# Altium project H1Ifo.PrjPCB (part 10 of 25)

## Sheet IfoIsc5A.SchDoc: D1800185
size C; Engineer: Daniel Sigg; DocumentNumber: 9; Revision: 4; SheetNumber: 9; SheetTotal: 11
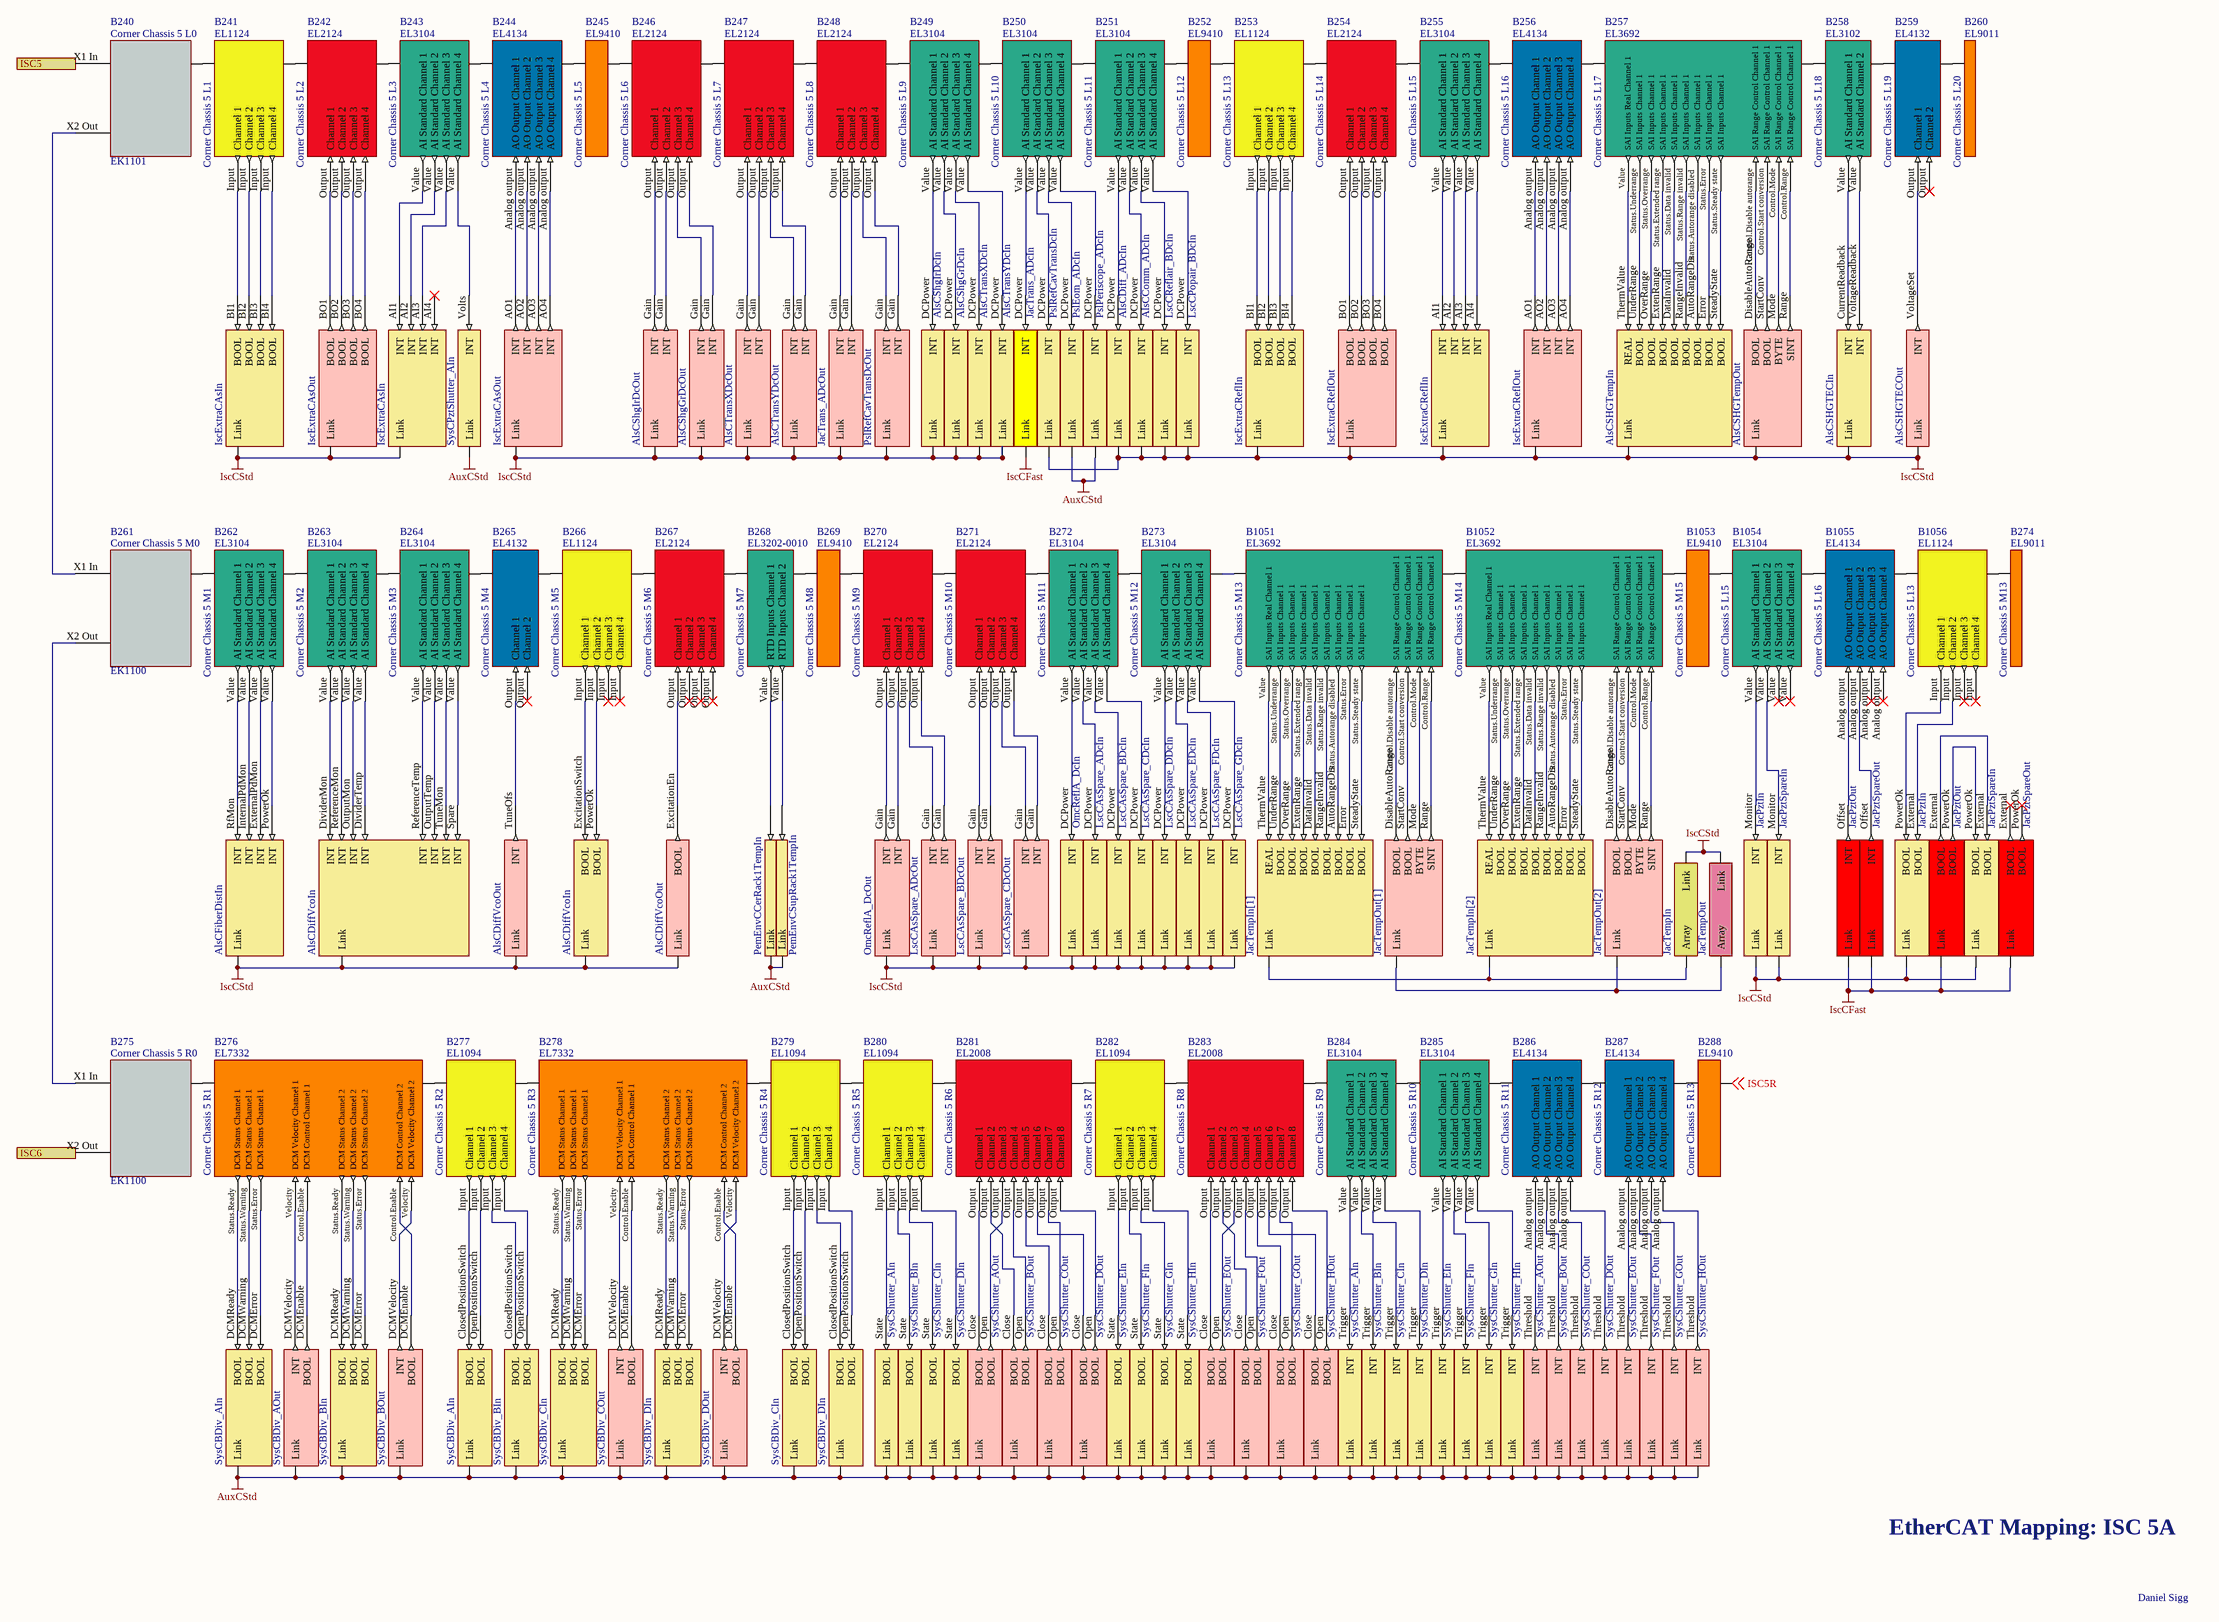
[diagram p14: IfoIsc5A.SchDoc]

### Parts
B240  Corner Chassis 5 L0  Part Number: EK1101  (mechanical)
B241  Corner Chassis 5 L1  Part Number: EL1124  (mechanical)
B242  Corner Chassis 5 L2  Part Number: EL2124  (mechanical)
B243  Corner Chassis 5 L3  Part Number: EL3104  (mechanical)
B244  Corner Chassis 5 L4  Part Number: EL4134  (mechanical)
B245  Corner Chassis 5 L5  Part Number: EL9410  (mechanical)
B246  Corner Chassis 5 L6  Part Number: EL2124  (mechanical)
B247  Corner Chassis 5 L7  Part Number: EL2124  (mechanical)
B248  Corner Chassis 5 L8  Part Number: EL2124  (mechanical)
B249  Corner Chassis 5 L9  Part Number: EL3104  (mechanical)
B250  Corner Chassis 5 L10  Part Number: EL3104  (mechanical)
B251  Corner Chassis 5 L11  Part Number: EL3104  (mechanical)
B252  Corner Chassis 5 L12  Part Number: EL9410  (mechanical)
B253  Corner Chassis 5 L13  Part Number: EL1124  (mechanical)
B254  Corner Chassis 5 L14  Part Number: EL2124  (mechanical)
B255  Corner Chassis 5 L15  Part Number: EL3104  (mechanical)
B256  Corner Chassis 5 L16  Part Number: EL4134  (mechanical)
B257  Corner Chassis 5 L17  Part Number: EL3692  (mechanical)
B258  Corner Chassis 5 L18  Part Number: EL3102  (mechanical)
B259  Corner Chassis 5 L19  Part Number: EL4132  (mechanical)
B260  Corner Chassis 5 L20  Part Number: EL9011  (mechanical)
B261  Corner Chassis 5 M0  Part Number: EK1100  (mechanical)
B262  Corner Chassis 5 M1  Part Number: EL3104  (mechanical)
B263  Corner Chassis 5 M2  Part Number: EL3104  (mechanical)
B264  Corner Chassis 5 M3  Part Number: EL3104  (mechanical)
B265  Corner Chassis 5 M4  Part Number: EL4132  (mechanical)
B266  Corner Chassis 5 M5  Part Number: EL1124  (mechanical)
B267  Corner Chassis 5 M6  Part Number: EL2124  (mechanical)
B268  Corner Chassis 5 M7  Part Number: EL3202-0010  (mechanical)
B269  Corner Chassis 5 M8  Part Number: EL9410  (mechanical)
B270  Corner Chassis 5 M9  Part Number: EL2124  (mechanical)
B271  Corner Chassis 5 M10  Part Number: EL2124  (mechanical)
B272  Corner Chassis 5 M11  Part Number: EL3104  (mechanical)
B273  Corner Chassis 5 M12  Part Number: EL3104  (mechanical)
B274  Corner Chassis 5 M13  Part Number: EL9011  (mechanical)
B275  Corner Chassis 5 R0  Part Number: EK1100  (mechanical)
B276  Corner Chassis 5 R1  Part Number: EL7332  (mechanical)
B277  Corner Chassis 5 R2  Part Number: EL1094  (mechanical)
B278  Corner Chassis 5 R3  Part Number: EL7332  (mechanical)
B279  Corner Chassis 5 R4  Part Number: EL1094  (mechanical)
B280  Corner Chassis 5 R5  Part Number: EL1094  (mechanical)
B281  Corner Chassis 5 R6  Part Number: EL2008  (mechanical)
B282  Corner Chassis 5 R7  Part Number: EL1094  (mechanical)
B283  Corner Chassis 5 R8  Part Number: EL2008  (mechanical)
B284  Corner Chassis 5 R9  Part Number: EL3104  (mechanical)
B285  Corner Chassis 5 R10  Part Number: EL3104  (mechanical)
B286  Corner Chassis 5 R11  Part Number: EL4134  (mechanical)
B287  Corner Chassis 5 R12  Part Number: EL4134  (mechanical)
B288  Corner Chassis 5 R13  Part Number: EL9410  (mechanical)
B1051  Corner Chassis 5 M13  Part Number: EL3692  (mechanical)
B1052  Corner Chassis 5 M14  Part Number: EL3692  (mechanical)
B1053  Corner Chassis 5 M15  Part Number: EL9410  (mechanical)
B1054  Corner Chassis 5 L15  Part Number: EL3104  (mechanical)
B1055  Corner Chassis 5 L16  Part Number: EL4134  (mechanical)
B1056  Corner Chassis 5 L13  Part Number: EL1124  (mechanical)
V215  SysCShutter_AIn  (parts A,B of 2)  (no BOM)
V216  SysCShutter_BIn  (parts A,B of 2)  (no BOM)
V217  SysCShutter_CIn  (parts A,B of 2)  (no BOM)
V218  SysCShutter_DIn  (parts A,B of 2)  (no BOM)
V219  SysCShutter_AOut  (parts A,B of 2)  (no BOM)
V220  SysCShutter_BOut  (parts A,B of 2)  (no BOM)
V221  SysCShutter_COut  (parts A,B of 2)  (no BOM)
V222  SysCShutter_DOut  (parts A,B of 2)  (no BOM)
V223  SysCShutter_EIn  (parts A,B of 2)  (no BOM)
V224  SysCShutter_FIn  (parts A,B of 2)  (no BOM)
V225  SysCShutter_GIn  (parts A,B of 2)  (no BOM)
V226  SysCShutter_HIn  (parts A,B of 2)  (no BOM)
V228  SysCShutter_EOut  (parts A,B of 2)  (no BOM)
V229  SysCShutter_FOut  (parts A,B of 2)  (no BOM)
V230  SysCShutter_GOut  (parts A,B of 2)  (no BOM)
V231  SysCShutter_HOut  (parts A,B of 2)  (no BOM)
V232  SysCBDiv_AIn  (parts A,B of 2)  (no BOM)
V233  SysCBDiv_BIn  (parts A,B of 2)  (no BOM)
V234  SysCBDiv_CIn  (parts A,B of 2)  (no BOM)
V235  SysCBDiv_DIn  (parts A,B of 2)  (no BOM)
V238  AlsCDiffVcoIn  (parts A,B of 2)  (no BOM)
V335  IscExtraCAsIn  (parts A,B of 2)  (no BOM)
V336  IscExtraCAsOut  (parts A,B of 2)  (no BOM)
V337  SysCPztShutter_AIn  (no BOM)
V338  AlsCShgIrDcOut  (no BOM)
V339  AlsCShgGrDcOut  (no BOM)
V340  AlsCTransXDcOut  (no BOM)
V341  AlsCTransYDcOut  (no BOM)
V342  JacTrans_ADcOut  (no BOM)
V343  PslRefCavTransDcOut  (no BOM)
V344  AlsCShgIrDcIn  (no BOM)
V345  AlsCShgGrDcIn  (no BOM)
V346  AlsCTransXDcIn  (no BOM)
V347  AlsCTransYDcIn  (no BOM)
V348  JacTrans_ADcIn  (no BOM)
V349  PslRefCavTransDcIn  (no BOM)
V350  PslEom_ADcIn  (no BOM)
V351  PslPeriscope_ADcIn  (no BOM)
V352  AlsCDiff_ADcIn  (no BOM)
V353  AlsCComm_ADcIn  (no BOM)
V354  LscCReflair_BDcIn  (no BOM)
V355  LscCPopair_BDcIn  (no BOM)
V376  IscExtraCReflIn  (parts A,B of 2)  (no BOM)
V377  IscExtraCReflOut  (parts A,B of 2)  (no BOM)
V378  AlsCFiberDistIn  (no BOM)
V379  AlsCDiffVcoOut  (parts A,B of 2)  (no BOM)
V382  PemEnvCCerRack1TempIn  (no BOM)
V383  PemEnvCSupRack1TempIn  (no BOM)
V384  LscCAsSpare_ADcOut  (no BOM)
V385  LscCAsSpare_BDcOut  (no BOM)
V386  LscCAsSpare_CDcOut  (no BOM)
V387  OmcReflA_DcOut  (no BOM)
V388  LscCAsSpare_ADcIn  (no BOM)
V389  LscCAsSpare_BDcIn  (no BOM)
V390  LscCAsSpare_CDcIn  (no BOM)
V391  LscCAsSpare_DDcIn  (no BOM)
V392  LscCAsSpare_EDcIn  (no BOM)
V393  LscCAsSpare_FDcIn  (no BOM)
V394  LscCAsSpare_GDcIn  (no BOM)
V395  OmcReflA_DcIn  (no BOM)
V396  SysCBDiv_AOut  (no BOM)
V397  SysCBDiv_BOut  (no BOM)
V398  SysCBDiv_COut  (no BOM)
V399  SysCBDiv_DOut  (no BOM)
V717  AlsCSHGTECIn  (no BOM)
V718  AlsCSHGTECOut  (no BOM)
V719  AlsCSHGTempIn  (no BOM)
V720  AlsCSHGTempOut  (no BOM)
V896  JacTempIn[1]  (no BOM)
V897  JacTempOut[1]  (no BOM)
V898  JacTempIn[2]  (no BOM)
V899  JacTempOut[2]  (no BOM)
V902  JacPztIn  (parts A,B of 2)  (no BOM)
V903  JacPztSpareIn  (parts A,B of 2)  (no BOM)
V904  JacPztOut  (parts A,B of 2)  (no BOM)
V905  JacPztSpareOut  (parts A,B of 2)  (no BOM)
V906  JacTempIn  (no BOM)
V907  JacTempOut  (no BOM)

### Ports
ISC5, ISC6

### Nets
AuxCStd: V215.0(Link) V215.1(Link) V216.0(Link) V216.1(Link) V217.0(Link) V217.1(Link) V218.0(Link) V218.1(Link) V219.0(Link) V219.1(Link) V220.0(Link) V220.1(Link) V221.0(Link) V221.1(Link) V222.0(Link) V222.1(Link) V223.0(Link) V223.1(Link) V224.0(Link) V224.1(Link) V225.0(Link) V225.1(Link) V226.0(Link) V226.1(Link) V228.0(Link) V228.1(Link) V229.0(Link) V229.1(Link) V230.0(Link) V230.1(Link) V231.0(Link) V231.1(Link) V232.0(Link) V232.1(Link) V233.0(Link) V233.1(Link) V234.0(Link) V234.1(Link) V235.0(Link) V235.1(Link) V337.1(Link) V350.1(Link) V351.1(Link) V382.?2(Link) V383.?2(Link) V396.0(Link) V397.0(Link) V398.0(Link) V399.0(Link)
IscCFast: V348.1(Link) V904.0(Link) V904.1(Link) V905.0(Link) V905.1(Link)
IscCStd: V238.0(Link) V238.1(Link) V335.0(Link) V335.1(Link) V336.0(Link) V336.1(Link) V338.0(Link) V339.0(Link) V340.0(Link) V341.0(Link) V342.0(Link) V343.0(Link) V344.1(Link) V345.1(Link) V346.1(Link) V347.1(Link) V349.1(Link) V352.1(Link) V353.1(Link) V354.1(Link) V355.1(Link) V376.0(Link) V376.1(Link) V377.0(Link) V377.1(Link) V378.1(Link) V379.0(Link) V379.1(Link) V384.0(Link) V385.0(Link) V386.0(Link) V387.0(Link) V388.1(Link) V389.1(Link) V390.1(Link) V391.1(Link) V392.1(Link) V393.1(Link) V394.1(Link) V395.1(Link) V717.1(Link) V718.1(Link) V719.1(Link) V720.1(Link) V902.0(Link) V902.1(Link) V903.0(Link) V903.1(Link) V906.?1(Link) V907.?1(Link)
ISC5R: B288.Ebus(B) ; off-sheet ISC5R
NetB234_X2 Out: B240.X1_In(A) ; port ISC5
NetB240_Ebus: B240.Ebus(B) B241.Ebus(A)
NetB240_X2 Out: B240.X2_Out(C) B261.X1_In(A)
NetB241_Ebus: B241.Ebus(B) B242.Ebus(A)
NetB241_Input: B241.Input(Channel_1) V335.BI1(BOOL)
NetB241_Input: B241.Input(Channel_2) V335.BI2(BOOL)  [a separate net that carries the same name]
NetB241_Input: B241.Input(Channel_3) V335.BI3(BOOL)  [a separate net that carries the same name]
NetB241_Input: B241.Input(Channel_4) V335.BI4(BOOL)  [a separate net that carries the same name]
NetB242_Ebus: B242.Ebus(B) B243.Ebus(A)
NetB242_Output: B242.Output(Channel_1) V336.BO1(BOOL)
NetB242_Output: B242.Output(Channel_2) V336.BO2(BOOL)  [a separate net that carries the same name]
NetB242_Output: B242.Output(Channel_3) V336.BO3(BOOL)  [a separate net that carries the same name]
NetB242_Output: B242.Output(Channel_4) V336.BO4(BOOL)  [a separate net that carries the same name]
NetB243_Ebus: B243.Ebus(B) B244.Ebus(A)
NetB243_Value: B243.Value(AI_Standard_Channel_1) V335.AI1(INT)
NetB243_Value: B243.Value(AI_Standard_Channel_2) V335.AI2(INT)  [a separate net that carries the same name]
NetB243_Value: B243.Value(AI_Standard_Channel_3) V335.AI3(INT)  [a separate net that carries the same name]
NetB243_Value: B243.Value(AI_Standard_Channel_4) V337.Volts(INT)  [a separate net that carries the same name]
NetB244_Analog output: B244.Analog_output(AO_Output_Channel_1) V336.AO1(INT)
NetB244_Analog output: B244.Analog_output(AO_Output_Channel_2) V336.AO2(INT)  [a separate net that carries the same name]
NetB244_Analog output: B244.Analog_output(AO_Output_Channel_3) V336.AO3(INT)  [a separate net that carries the same name]
NetB244_Analog output: B244.Analog_output(AO_Output_Channel_4) V336.AO4(INT)  [a separate net that carries the same name]
NetB244_Ebus: B244.Ebus(B) B245.Ebus(A)
NetB245_Ebus: B245.Ebus(B) B246.Ebus(A)
NetB246_Ebus: B246.Ebus(B) B247.Ebus(A)
NetB246_Output: B246.Output(Channel_1) V338.Gain(INT)
NetB246_Output: B246.Output(Channel_2) V338.Gain(INT)  [a separate net that carries the same name]
NetB246_Output: B246.Output(Channel_3) V339.Gain(INT)  [a separate net that carries the same name]
NetB246_Output: B246.Output(Channel_4) V339.Gain(INT)  [a separate net that carries the same name]
NetB247_Ebus: B247.Ebus(B) B248.Ebus(A)
NetB247_Output: B247.Output(Channel_1) V340.Gain(INT)
NetB247_Output: B247.Output(Channel_2) V340.Gain(INT)  [a separate net that carries the same name]
NetB247_Output: B247.Output(Channel_3) V341.Gain(INT)  [a separate net that carries the same name]
NetB247_Output: B247.Output(Channel_4) V341.Gain(INT)  [a separate net that carries the same name]
NetB248_Ebus: B248.Ebus(B) B249.Ebus(A)
NetB248_Output: B248.Output(Channel_1) V342.Gain(INT)
NetB248_Output: B248.Output(Channel_2) V342.Gain(INT)  [a separate net that carries the same name]
NetB248_Output: B248.Output(Channel_3) V343.Gain(INT)  [a separate net that carries the same name]
NetB248_Output: B248.Output(Channel_4) V343.Gain(INT)  [a separate net that carries the same name]
NetB249_Ebus: B249.Ebus(B) B250.Ebus(A)
NetB249_Value: B249.Value(AI_Standard_Channel_1) V344.DCPower(INT)
NetB249_Value: B249.Value(AI_Standard_Channel_2) V345.DCPower(INT)  [a separate net that carries the same name]
NetB249_Value: B249.Value(AI_Standard_Channel_3) V346.DCPower(INT)  [a separate net that carries the same name]
NetB249_Value: B249.Value(AI_Standard_Channel_4) V347.DCPower(INT)  [a separate net that carries the same name]
NetB250_Ebus: B250.Ebus(B) B251.Ebus(A)
NetB250_Value: B250.Value(AI_Standard_Channel_1) V348.DCPower(INT)
NetB250_Value: B250.Value(AI_Standard_Channel_2) V349.DCPower(INT)  [a separate net that carries the same name]
NetB250_Value: B250.Value(AI_Standard_Channel_3) V350.DCPower(INT)  [a separate net that carries the same name]
NetB250_Value: B250.Value(AI_Standard_Channel_4) V351.DCPower(INT)  [a separate net that carries the same name]
NetB251_Ebus: B251.Ebus(B) B252.Ebus(A)
NetB251_Value: B251.Value(AI_Standard_Channel_1) V352.DCPower(INT)
NetB251_Value: B251.Value(AI_Standard_Channel_2) V353.DCPower(INT)  [a separate net that carries the same name]
NetB251_Value: B251.Value(AI_Standard_Channel_3) V354.DCPower(INT)  [a separate net that carries the same name]
NetB251_Value: B251.Value(AI_Standard_Channel_4) V355.DCPower(INT)  [a separate net that carries the same name]
NetB252_Ebus: B252.Ebus(B) B253.Ebus(A)
NetB253_Ebus: B253.Ebus(B) B254.Ebus(A)
NetB253_Input: B253.Input(Channel_1) V376.BI1(BOOL)
NetB253_Input: B253.Input(Channel_2) V376.BI2(BOOL)  [a separate net that carries the same name]
NetB253_Input: B253.Input(Channel_3) V376.BI3(BOOL)  [a separate net that carries the same name]
NetB253_Input: B253.Input(Channel_4) V376.BI4(BOOL)  [a separate net that carries the same name]
NetB254_Ebus: B254.Ebus(B) B255.Ebus(A)
NetB254_Output: B254.Output(Channel_1) V377.BO1(BOOL)
NetB254_Output: B254.Output(Channel_2) V377.BO2(BOOL)  [a separate net that carries the same name]
NetB254_Output: B254.Output(Channel_3) V377.BO3(BOOL)  [a separate net that carries the same name]
NetB254_Output: B254.Output(Channel_4) V377.BO4(BOOL)  [a separate net that carries the same name]
NetB255_Ebus: B255.Ebus(B) B256.Ebus(A)
NetB255_Value: B255.Value(AI_Standard_Channel_1) V376.AI1(INT)
NetB255_Value: B255.Value(AI_Standard_Channel_2) V376.AI2(INT)  [a separate net that carries the same name]
NetB255_Value: B255.Value(AI_Standard_Channel_3) V376.AI3(INT)  [a separate net that carries the same name]
NetB255_Value: B255.Value(AI_Standard_Channel_4) V376.AI4(INT)  [a separate net that carries the same name]
NetB256_Analog output: B256.Analog_output(AO_Output_Channel_1) V377.AO1(INT)
NetB256_Analog output: B256.Analog_output(AO_Output_Channel_2) V377.AO2(INT)  [a separate net that carries the same name]
NetB256_Analog output: B256.Analog_output(AO_Output_Channel_3) V377.AO3(INT)  [a separate net that carries the same name]
NetB256_Analog output: B256.Analog_output(AO_Output_Channel_4) V377.AO4(INT)  [a separate net that carries the same name]
NetB256_Ebus: B256.Ebus(B) B257.Ebus(A)
NetB257_Control.Disable autorange: B257.Control.Disable_autorange(SAI_Range_Control_Channel_1) V720.DisableAutoRange(BOOL)
NetB257_Control.Mode: B257.Control.Mode(SAI_Range_Control_Channel_1) V720.Mode(BYTE)
NetB257_Control.Range: B257.Control.Range(SAI_Range_Control_Channel_1) V720.Range(SINT)
NetB257_Control.Start conversion: B257.Control.Start_conversion(SAI_Range_Control_Channel_1) V720.StartConv(BOOL)
NetB257_Ebus: B257.Ebus(B) B258.Ebus(A)
NetB257_Status.Autorange disabled: B257.Status.Autorange_disabled(SAI_Inputs_Channel_1) V719.AutoRangeDis(BOOL)
NetB257_Status.Data invalid: B257.Status.Data_invalid(SAI_Inputs_Channel_1) V719.DataInvalid(BOOL)
NetB257_Status.Error: B257.Status.Error(SAI_Inputs_Channel_1) V719.Error(BOOL)
NetB257_Status.Extended range: B257.Status.Extended_range(SAI_Inputs_Channel_1) V719.ExtenRange(BOOL)
NetB257_Status.Overrange: B257.Status.Overrange(SAI_Inputs_Channel_1) V719.OverRange(BOOL)
NetB257_Status.Range invalid: B257.Status.Range_invalid(SAI_Inputs_Channel_1) V719.RangeInvalid(BOOL)
NetB257_Status.Steady state: B257.Status.Steady_state(SAI_Inputs_Channel_1) V719.SteadyState(BOOL)
NetB257_Status.Underrange: B257.Status.Underrange(SAI_Inputs_Channel_1) V719.UnderRange(BOOL)
NetB257_Value: B257.Value(SAI_Inputs_Real_Channel_1) V719.ThermValue(REAL)
NetB258_Ebus: B258.Ebus(B) B259.Ebus(A)
NetB258_Value: B258.Value(AI_Standard_Channel_1) V717.CurrentReadback(INT)
NetB258_Value: B258.Value(AI_Standard_Channel_2) V717.VoltageReadback(INT)  [a separate net that carries the same name]
NetB259_Ebus: B259.Ebus(B) B260.Ebus(A)
NetB259_Output: B259.Output(Channel_1) V718.VoltageSet(INT)
NetB261_Ebus: B261.Ebus(B) B262.Ebus(A)
NetB261_X2 Out: B261.X2_Out(C) B275.X1_In(A)
NetB262_Ebus: B262.Ebus(B) B263.Ebus(A)
NetB262_Value: B262.Value(AI_Standard_Channel_1) V378.RfMon(INT)
NetB262_Value: B262.Value(AI_Standard_Channel_2) V378.InternalPdMon(INT)  [a separate net that carries the same name]
NetB262_Value: B262.Value(AI_Standard_Channel_3) V378.ExternalPdMon(INT)  [a separate net that carries the same name]
NetB262_Value: B262.Value(AI_Standard_Channel_4) V378.PowerOk(INT)  [a separate net that carries the same name]
NetB263_Ebus: B263.Ebus(B) B264.Ebus(A)
NetB263_Value: B263.Value(AI_Standard_Channel_1) V238.DividerMon(INT)
NetB263_Value: B263.Value(AI_Standard_Channel_2) V238.ReferenceMon(INT)  [a separate net that carries the same name]
NetB263_Value: B263.Value(AI_Standard_Channel_3) V238.OutputMon(INT)  [a separate net that carries the same name]
NetB263_Value: B263.Value(AI_Standard_Channel_4) V238.DividerTemp(INT)  [a separate net that carries the same name]
NetB264_Ebus: B264.Ebus(B) B265.Ebus(A)
NetB264_Value: B264.Value(AI_Standard_Channel_1) V238.ReferenceTemp(INT)
NetB264_Value: B264.Value(AI_Standard_Channel_2) V238.OutputTemp(INT)  [a separate net that carries the same name]
NetB264_Value: B264.Value(AI_Standard_Channel_3) V238.TuneMon(INT)  [a separate net that carries the same name]
NetB264_Value: B264.Value(AI_Standard_Channel_4) V238.Spare(INT)  [a separate net that carries the same name]
NetB265_Ebus: B265.Ebus(B) B266.Ebus(A)
NetB265_Output: B265.Output(Channel_1) V379.TuneOfs(INT)
NetB266_Ebus: B266.Ebus(B) B267.Ebus(A)
NetB266_Input: B266.Input(Channel_1) V238.ExcitationSwitch(BOOL)
NetB266_Input: B266.Input(Channel_2) V238.PowerOk(BOOL)  [a separate net that carries the same name]
NetB267_Ebus: B267.Ebus(B) B268.Ebus(A)
NetB267_Output: B267.Output(Channel_1) V379.ExcitationEn(BOOL)
NetB268_Ebus: B268.Ebus(B) B269.Ebus(A)
NetB268_Value: B268.Value(RTD_Inputs_Channel_1) V382.?1
NetB268_Value: B268.Value(RTD_Inputs_Channel_2) V383.?1  [a separate net that carries the same name]
NetB269_Ebus: B269.Ebus(B) B270.Ebus(A)
NetB270_Ebus: B270.Ebus(B) B271.Ebus(A)
NetB270_Output: B270.Output(Channel_1) V387.Gain(INT)
NetB270_Output: B270.Output(Channel_2) V387.Gain(INT)  [a separate net that carries the same name]
NetB270_Output: B270.Output(Channel_3) V384.Gain(INT)  [a separate net that carries the same name]
NetB270_Output: B270.Output(Channel_4) V384.Gain(INT)  [a separate net that carries the same name]
NetB271_Ebus: B271.Ebus(B) B272.Ebus(A)
NetB271_Output: B271.Output(Channel_1) V385.Gain(INT)
NetB271_Output: B271.Output(Channel_2) V385.Gain(INT)  [a separate net that carries the same name]
NetB271_Output: B271.Output(Channel_3) V386.Gain(INT)  [a separate net that carries the same name]
NetB271_Output: B271.Output(Channel_4) V386.Gain(INT)  [a separate net that carries the same name]
NetB272_Ebus: B272.Ebus(B) B273.Ebus(A)
NetB272_Value: B272.Value(AI_Standard_Channel_1) V395.DCPower(INT)
NetB272_Value: B272.Value(AI_Standard_Channel_2) V388.DCPower(INT)  [a separate net that carries the same name]
NetB272_Value: B272.Value(AI_Standard_Channel_3) V389.DCPower(INT)  [a separate net that carries the same name]
NetB272_Value: B272.Value(AI_Standard_Channel_4) V390.DCPower(INT)  [a separate net that carries the same name]
NetB273_Ebus: B273.Ebus(B) B1051.Ebus(A)
NetB273_Value: B273.Value(AI_Standard_Channel_1) V391.DCPower(INT)
NetB273_Value: B273.Value(AI_Standard_Channel_2) V392.DCPower(INT)  [a separate net that carries the same name]
NetB273_Value: B273.Value(AI_Standard_Channel_3) V393.DCPower(INT)  [a separate net that carries the same name]
NetB273_Value: B273.Value(AI_Standard_Channel_4) V394.DCPower(INT)  [a separate net that carries the same name]
NetB274_Ebus: B274.Ebus(A) B1056.Ebus(B)
NetB275_Ebus: B275.Ebus(B) B276.Ebus(A)
NetB275_X2 Out: B275.X2_Out(C) ; port ISC6
NetB276_Control.Enable: B276.Control.Enable(DCM_Control_Channel_1) V396.DCMEnable(BOOL)
NetB276_Control.Enable: B276.Control.Enable(DCM_Control_Channel_2) V397.DCMEnable(BOOL)  [a separate net that carries the same name]
NetB276_Ebus: B276.Ebus(B) B277.Ebus(A)
NetB276_Status.Error: B276.Status.Error(DCM_Status_Channel_1) V232.DCMError(BOOL)
NetB276_Status.Error: B276.Status.Error(DCM_Status_Channel_2) V233.DCMError(BOOL)  [a separate net that carries the same name]
NetB276_Status.Ready: B276.Status.Ready(DCM_Status_Channel_1) V232.DCMReady(BOOL)
NetB276_Status.Ready: B276.Status.Ready(DCM_Status_Channel_2) V233.DCMReady(BOOL)  [a separate net that carries the same name]
NetB276_Status.Warning: B276.Status.Warning(DCM_Status_Channel_1) V232.DCMWarning(BOOL)
NetB276_Status.Warning: B276.Status.Warning(DCM_Status_Channel_2) V233.DCMWarning(BOOL)  [a separate net that carries the same name]
NetB276_Velocity: B276.Velocity(DCM_Velocity_Channel_1) V396.DCMVelocity(INT)
NetB276_Velocity: B276.Velocity(DCM_Velocity_Channel_2) V397.DCMVelocity(INT)  [a separate net that carries the same name]
NetB277_Ebus: B277.Ebus(B) B278.Ebus(A)
NetB277_Input: B277.Input(Channel_1) V232.ClosedPositionSwitch(BOOL)
NetB277_Input: B277.Input(Channel_2) V232.OpenPositionSwitch(BOOL)  [a separate net that carries the same name]
NetB277_Input: B277.Input(Channel_3) V233.ClosedPositionSwitch(BOOL)  [a separate net that carries the same name]
NetB277_Input: B277.Input(Channel_4) V233.OpenPositionSwitch(BOOL)  [a separate net that carries the same name]
NetB278_Control.Enable: B278.Control.Enable(DCM_Control_Channel_1) V398.DCMEnable(BOOL)
NetB278_Control.Enable: B278.Control.Enable(DCM_Control_Channel_2) V399.DCMEnable(BOOL)  [a separate net that carries the same name]
NetB278_Ebus: B278.Ebus(B) B279.Ebus(A)
NetB278_Status.Error: B278.Status.Error(DCM_Status_Channel_1) V234.DCMError(BOOL)
NetB278_Status.Error: B278.Status.Error(DCM_Status_Channel_2) V235.DCMError(BOOL)  [a separate net that carries the same name]
NetB278_Status.Ready: B278.Status.Ready(DCM_Status_Channel_1) V234.DCMReady(BOOL)
NetB278_Status.Ready: B278.Status.Ready(DCM_Status_Channel_2) V235.DCMReady(BOOL)  [a separate net that carries the same name]
NetB278_Status.Warning: B278.Status.Warning(DCM_Status_Channel_1) V234.DCMWarning(BOOL)
NetB278_Status.Warning: B278.Status.Warning(DCM_Status_Channel_2) V235.DCMWarning(BOOL)  [a separate net that carries the same name]
NetB278_Velocity: B278.Velocity(DCM_Velocity_Channel_1) V398.DCMVelocity(INT)
NetB278_Velocity: B278.Velocity(DCM_Velocity_Channel_2) V399.DCMVelocity(INT)  [a separate net that carries the same name]
NetB279_Ebus: B279.Ebus(B) B280.Ebus(A)
NetB279_Input: B279.Input(Channel_1) V234.ClosedPositionSwitch(BOOL)
NetB279_Input: B279.Input(Channel_2) V234.OpenPositionSwitch(BOOL)  [a separate net that carries the same name]
NetB279_Input: B279.Input(Channel_3) V235.ClosedPositionSwitch(BOOL)  [a separate net that carries the same name]
NetB279_Input: B279.Input(Channel_4) V235.OpenPositionSwitch(BOOL)  [a separate net that carries the same name]
NetB280_Ebus: B280.Ebus(B) B281.Ebus(A)
NetB280_Input: B280.Input(Channel_1) V215.State(BOOL)
NetB280_Input: B280.Input(Channel_2) V216.State(BOOL)  [a separate net that carries the same name]
NetB280_Input: B280.Input(Channel_3) V217.State(BOOL)  [a separate net that carries the same name]
NetB280_Input: B280.Input(Channel_4) V218.State(BOOL)  [a separate net that carries the same name]
NetB281_Ebus: B281.Ebus(B) B282.Ebus(A)
NetB281_Output: B281.Output(Channel_1) V219.Close(BOOL)
NetB281_Output: B281.Output(Channel_2) V220.Close(BOOL)  [a separate net that carries the same name]
NetB281_Output: B281.Output(Channel_3) V219.Open(BOOL)  [a separate net that carries the same name]
NetB281_Output: B281.Output(Channel_4) V220.Open(BOOL)  [a separate net that carries the same name]
NetB281_Output: B281.Output(Channel_5) V221.Close(BOOL)  [a separate net that carries the same name]
NetB281_Output: B281.Output(Channel_6) V222.Close(BOOL)  [a separate net that carries the same name]
NetB281_Output: B281.Output(Channel_7) V221.Open(BOOL)  [a separate net that carries the same name]
NetB281_Output: B281.Output(Channel_8) V222.Open(BOOL)  [a separate net that carries the same name]
NetB282_Ebus: B282.Ebus(B) B283.Ebus(A)
NetB282_Input: B282.Input(Channel_1) V223.State(BOOL)
NetB282_Input: B282.Input(Channel_2) V224.State(BOOL)  [a separate net that carries the same name]
NetB282_Input: B282.Input(Channel_3) V225.State(BOOL)  [a separate net that carries the same name]
NetB282_Input: B282.Input(Channel_4) V226.State(BOOL)  [a separate net that carries the same name]
NetB283_Ebus: B283.Ebus(B) B284.Ebus(A)
NetB283_Output: B283.Output(Channel_1) V228.Close(BOOL)
NetB283_Output: B283.Output(Channel_2) V229.Close(BOOL)  [a separate net that carries the same name]
NetB283_Output: B283.Output(Channel_3) V228.Open(BOOL)  [a separate net that carries the same name]
NetB283_Output: B283.Output(Channel_4) V229.Open(BOOL)  [a separate net that carries the same name]
NetB283_Output: B283.Output(Channel_5) V230.Close(BOOL)  [a separate net that carries the same name]
NetB283_Output: B283.Output(Channel_6) V231.Close(BOOL)  [a separate net that carries the same name]
NetB283_Output: B283.Output(Channel_7) V230.Open(BOOL)  [a separate net that carries the same name]
NetB283_Output: B283.Output(Channel_8) V231.Open(BOOL)  [a separate net that carries the same name]
NetB284_Ebus: B284.Ebus(B) B285.Ebus(A)
NetB284_Value: B284.Value(AI_Standard_Channel_1) V215.Trigger(INT)
NetB284_Value: B284.Value(AI_Standard_Channel_2) V216.Trigger(INT)  [a separate net that carries the same name]
NetB284_Value: B284.Value(AI_Standard_Channel_3) V217.Trigger(INT)  [a separate net that carries the same name]
NetB284_Value: B284.Value(AI_Standard_Channel_4) V218.Trigger(INT)  [a separate net that carries the same name]
NetB285_Ebus: B285.Ebus(B) B286.Ebus(A)
NetB285_Value: B285.Value(AI_Standard_Channel_1) V223.Trigger(INT)
NetB285_Value: B285.Value(AI_Standard_Channel_2) V224.Trigger(INT)  [a separate net that carries the same name]
NetB285_Value: B285.Value(AI_Standard_Channel_3) V225.Trigger(INT)  [a separate net that carries the same name]
NetB285_Value: B285.Value(AI_Standard_Channel_4) V226.Trigger(INT)  [a separate net that carries the same name]
NetB286_Analog output: B286.Analog_output(AO_Output_Channel_1) V219.Threshold(INT)
NetB286_Analog output: B286.Analog_output(AO_Output_Channel_2) V220.Threshold(INT)  [a separate net that carries the same name]
NetB286_Analog output: B286.Analog_output(AO_Output_Channel_3) V221.Threshold(INT)  [a separate net that carries the same name]
NetB286_Analog output: B286.Analog_output(AO_Output_Channel_4) V222.Threshold(INT)  [a separate net that carries the same name]
NetB286_Ebus: B286.Ebus(B) B287.Ebus(A)
NetB287_Analog output: B287.Analog_output(AO_Output_Channel_1) V228.Threshold(INT)
NetB287_Analog output: B287.Analog_output(AO_Output_Channel_2) V229.Threshold(INT)  [a separate net that carries the same name]
NetB287_Analog output: B287.Analog_output(AO_Output_Channel_3) V230.Threshold(INT)  [a separate net that carries the same name]
NetB287_Analog output: B287.Analog_output(AO_Output_Channel_4) V231.Threshold(INT)  [a separate net that carries the same name]
NetB287_Ebus: B287.Ebus(B) B288.Ebus(A)
NetB1051_Control.Disable autorange: B1051.Control.Disable_autorange(SAI_Range_Control_Channel_1) V897.DisableAutoRange(BOOL)
NetB1051_Control.Mode: B1051.Control.Mode(SAI_Range_Control_Channel_1) V897.Mode(BYTE)
NetB1051_Control.Range: B1051.Control.Range(SAI_Range_Control_Channel_1) V897.Range(SINT)
NetB1051_Control.Start conversion: B1051.Control.Start_conversion(SAI_Range_Control_Channel_1) V897.StartConv(BOOL)
NetB1051_Ebus: B1051.Ebus(B) B1052.Ebus(A)
NetB1051_Status.Autorange disabled: B1051.Status.Autorange_disabled(SAI_Inputs_Channel_1) V896.AutoRangeDis(BOOL)
NetB1051_Status.Data invalid: B1051.Status.Data_invalid(SAI_Inputs_Channel_1) V896.DataInvalid(BOOL)
NetB1051_Status.Error: B1051.Status.Error(SAI_Inputs_Channel_1) V896.Error(BOOL)
NetB1051_Status.Extended range: B1051.Status.Extended_range(SAI_Inputs_Channel_1) V896.ExtenRange(BOOL)
NetB1051_Status.Overrange: B1051.Status.Overrange(SAI_Inputs_Channel_1) V896.OverRange(BOOL)
NetB1051_Status.Range invalid: B1051.Status.Range_invalid(SAI_Inputs_Channel_1) V896.RangeInvalid(BOOL)
NetB1051_Status.Steady state: B1051.Status.Steady_state(SAI_Inputs_Channel_1) V896.SteadyState(BOOL)
NetB1051_Status.Underrange: B1051.Status.Underrange(SAI_Inputs_Channel_1) V896.UnderRange(BOOL)
NetB1051_Value: B1051.Value(SAI_Inputs_Real_Channel_1) V896.ThermValue(REAL)
NetB1052_Control.Disable autorange: B1052.Control.Disable_autorange(SAI_Range_Control_Channel_1) V899.DisableAutoRange(BOOL)
NetB1052_Control.Mode: B1052.Control.Mode(SAI_Range_Control_Channel_1) V899.Mode(BYTE)
NetB1052_Control.Range: B1052.Control.Range(SAI_Range_Control_Channel_1) V899.Range(SINT)
NetB1052_Control.Start conversion: B1052.Control.Start_conversion(SAI_Range_Control_Channel_1) V899.StartConv(BOOL)
NetB1052_Ebus: B1052.Ebus(B) B1053.Ebus(A)
NetB1052_Status.Autorange disabled: B1052.Status.Autorange_disabled(SAI_Inputs_Channel_1) V898.AutoRangeDis(BOOL)
NetB1052_Status.Data invalid: B1052.Status.Data_invalid(SAI_Inputs_Channel_1) V898.DataInvalid(BOOL)
NetB1052_Status.Error: B1052.Status.Error(SAI_Inputs_Channel_1) V898.Error(BOOL)
NetB1052_Status.Extended range: B1052.Status.Extended_range(SAI_Inputs_Channel_1) V898.ExtenRange(BOOL)
NetB1052_Status.Overrange: B1052.Status.Overrange(SAI_Inputs_Channel_1) V898.OverRange(BOOL)
NetB1052_Status.Range invalid: B1052.Status.Range_invalid(SAI_Inputs_Channel_1) V898.RangeInvalid(BOOL)
NetB1052_Status.Steady state: B1052.Status.Steady_state(SAI_Inputs_Channel_1) V898.SteadyState(BOOL)
NetB1052_Status.Underrange: B1052.Status.Underrange(SAI_Inputs_Channel_1) V898.UnderRange(BOOL)
NetB1052_Value: B1052.Value(SAI_Inputs_Real_Channel_1) V898.ThermValue(REAL)
NetB1053_Ebus: B1053.Ebus(B) B1054.Ebus(A)
NetB1054_Ebus: B1054.Ebus(B) B1055.Ebus(A)
NetB1054_Value: B1054.Value(AI_Standard_Channel_1) V902.Monitor(INT)
NetB1054_Value: B1054.Value(AI_Standard_Channel_2) V903.Monitor(INT)  [a separate net that carries the same name]
NetB1055_Analog output: B1055.Analog_output(AO_Output_Channel_1) V904.Offset(INT)
NetB1055_Analog output: B1055.Analog_output(AO_Output_Channel_2) V905.Offset(INT)  [a separate net that carries the same name]
NetB1055_Ebus: B1055.Ebus(B) B1056.Ebus(A)
NetB1056_Input: B1056.Input(Channel_1) V902.PowerOk(BOOL)
NetB1056_Input: B1056.Input(Channel_2) V902.External(BOOL)  [a separate net that carries the same name]
NetV896_1: V896.1(Link) V898.1(Link) V906.?2(Array)
NetV897_1: V897.1(Link) V899.1(Link) V907.?2(Array)
NetV903_External: V903.External(BOOL) V904.External(BOOL)
NetV903_PowerOk: V903.PowerOk(BOOL) V904.PowerOk(BOOL)

Not connected (* = marked no-connect by the designer): V335 AI4(INT)*; V905 External(BOOL)* PowerOk(BOOL)*

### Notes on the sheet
- EtherCAT Mapping: ISC 5A
- Daniel Sigg

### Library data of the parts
B240 = CouplerEK1101: EtherCAT Coupler; Rail: Left; BoxNextB: BNHETBHX; BoxNextC: RDWQKENG; BoxPrev: YDPMJXXR; PortPrevFull: 1185/C; PortPrevShort: C 'X2 Out'; Fullname: TIID^Vertex ISC (EtherCAT)^Corner Chassis 5 L0 (EK1101); BoxPorts: Junction; BoxAddr: 1190; Disabled: False
B241 = TerminalEL1124: EtherCAT Terminal EL1124 4-chn Digital Input; Rail: Left; BoxNextB: VYULUJTV; BoxPrev: FCKUDXRC; PortPrevFull: 1190/B; PortPrevShort: B; Fullname: TIID^Vertex ISC (EtherCAT)^Corner Chassis 5 L0 (EK1101)^Corner Chassis 5 L1 (EL1124); BoxAddr: 1191; Disabled: False
B242 = TerminalEL2124: EtherCAT Terminal EL2124 4-chn Digital Ouput; Rail: Left; BoxNextB: OKRTLGOD; BoxPrev: BNHETBHX; PortPrevFull: 1191/B; PortPrevShort: B; Fullname: TIID^Vertex ISC (EtherCAT)^Corner Chassis 5 L0 (EK1101)^Corner Chassis 5 L2 (EL2124); BoxAddr: 1192; Disabled: False
B243 = TerminalEL3104: EtherCAT Terminal EL3104 4-chn Analog Input; Rail: Left; BoxNextB: ADMFJSAS; BoxPrev: VYULUJTV; PortPrevFull: 1192/B; PortPrevShort: B; Fullname: TIID^Vertex ISC (EtherCAT)^Corner Chassis 5 L0 (EK1101)^Corner Chassis 5 L3 (EL3104); BoxAddr: 1193; Disabled: False
B244 = TerminalEL4134: EtherCAT Terminal EL4134 4-chn Analog Ouput; Rail: Left; BoxNextB: RNHXJNIV; BoxPrev: OKRTLGOD; PortPrevFull: 1193/B; PortPrevShort: B; Fullname: TIID^Vertex ISC (EtherCAT)^Corner Chassis 5 L0 (EK1101)^Corner Chassis 5 L4 (EL4134); BoxAddr: 1194; Disabled: False
B245 B252 B269 B1053 = TerminalEL9410: EtherCAT Terminal EL9410 Power; Rail: Left; BoxNextB: FMFEXFWC; BoxPrev: DJUMQFPO; PortPrevFull: 1200/B; PortPrevShort: B; Fullname: TIID^Vertex ISC (EtherCAT)^Corner Chassis 5 L0 (EK1101)^Corner Chassis 5 L12 (EL9410); BoxAddr: 1201; Disabled: False
B246 = TerminalEL2124: EtherCAT Terminal EL2124 4-chn Digital Ouput; Rail: Left; BoxNextB: YEUSVXUX; BoxPrev: RNHXJNIV; PortPrevFull: 1194/B; PortPrevShort: B; Fullname: TIID^Vertex ISC (EtherCAT)^Corner Chassis 5 L0 (EK1101)^Corner Chassis 5 L6 (EL2124); BoxAddr: 1195; Disabled: False
B247 = TerminalEL2124: EtherCAT Terminal EL2124 4-chn Digital Ouput; Rail: Left; BoxNextB: UWNEVDYM; BoxPrev: CDVEYTSJ; PortPrevFull: 1195/B; PortPrevShort: B; Fullname: TIID^Vertex ISC (EtherCAT)^Corner Chassis 5 L0 (EK1101)^Corner Chassis 5 L7 (EL2124); BoxAddr: 1196; Disabled: False
B248 = TerminalEL2124: EtherCAT Terminal EL2124 4-chn Digital Ouput; Rail: Left; BoxNextB: UENEMDEG; BoxPrev: YEUSVXUX; PortPrevFull: 1196/B; PortPrevShort: B; Fullname: TIID^Vertex ISC (EtherCAT)^Corner Chassis 5 L0 (EK1101)^Corner Chassis 5 L8 (EL2124); BoxAddr: 1197; Disabled: False
B249 = TerminalEL3104: EtherCAT Terminal EL3104 4-chn Analog Input; Rail: Left; BoxNextB: ALNVXWWM; BoxPrev: UWNEVDYM; PortPrevFull: 1197/B; PortPrevShort: B; Fullname: TIID^Vertex ISC (EtherCAT)^Corner Chassis 5 L0 (EK1101)^Corner Chassis 5 L9 (EL3104); BoxAddr: 1198; Disabled: False
B250 = TerminalEL3104: EtherCAT Terminal EL3104 4-chn Analog Input; Rail: Left; BoxNextB: DJUMQFPO; BoxPrev: UENEMDEG; PortPrevFull: 1198/B; PortPrevShort: B; Fullname: TIID^Vertex ISC (EtherCAT)^Corner Chassis 5 L0 (EK1101)^Corner Chassis 5 L10 (EL3104); BoxAddr: 1199; Disabled: False
B251 = TerminalEL3104: EtherCAT Terminal EL3104 4-chn Analog Input; Rail: Left; BoxNextB: GCGQECRW; BoxPrev: ALNVXWWM; PortPrevFull: 1199/B; PortPrevShort: B; Fullname: TIID^Vertex ISC (EtherCAT)^Corner Chassis 5 L0 (EK1101)^Corner Chassis 5 L11 (EL3104); BoxAddr: 1200; Disabled: False
B253 B1056 = TerminalEL1124: EtherCAT Terminal EL1124 4-chn Digital Input; Rail: Left; BoxNextB: YJTYSYUV; BoxPrev: GCGQECRW; PortPrevFull: 1201/B; PortPrevShort: B; Fullname: TIID^Vertex ISC (EtherCAT)^Corner Chassis 5 L0 (EK1101)^Corner Chassis 5 L13 (EL1124); BoxAddr: 1202; Disabled: False
B254 = TerminalEL2124: EtherCAT Terminal EL2124 4-chn Digital Ouput; Rail: Left; BoxNextB: UKXCNGKQ; BoxPrev: FMFEXFWC; PortPrevFull: 1202/B; PortPrevShort: B; Fullname: TIID^Vertex ISC (EtherCAT)^Corner Chassis 5 L0 (EK1101)^Corner Chassis 5 L14 (EL2124); BoxAddr: 1203; Disabled: False
B255 B1054 = TerminalEL3104: EtherCAT Terminal EL3104 4-chn Analog Input; Rail: Left; BoxNextB: WGCBOMOA; BoxPrev: YJTYSYUV; PortPrevFull: 1203/B; PortPrevShort: B; Fullname: TIID^Vertex ISC (EtherCAT)^Corner Chassis 5 L0 (EK1101)^Corner Chassis 5 L15 (EL3104); BoxAddr: 1204; Disabled: False
B256 B1055 = TerminalEL4134: EtherCAT Terminal EL4134 4-chn Analog Ouput; Rail: Left; BoxNextB: SPCCPAUO; BoxPrev: UKXCNGKQ; PortPrevFull: 1204/B; PortPrevShort: B; Fullname: TIID^Vertex ISC (EtherCAT)^Corner Chassis 5 L0 (EK1101)^Corner Chassis 5 L16 (EL4134); BoxAddr: 1205; Disabled: False
B257 B1051 B1052 = TerminalEL3692-1chn: EtherCAT Terminal EL3692 1-chn Resistance Measurement; Rail: Left; BoxNextB: TMLCPOEL; BoxPrev: WGCBOMOA; PortPrevFull: 1205/B; PortPrevShort: B; Fullname: TIID^Vertex ISC (EtherCAT)^Corner Chassis 5 L0 (EK1101)^Corner Chassis 5 L17 (EL3692); BoxAddr: 1206; PDO Inputs: 0x1A00,0x1A02; PDO Outputs: 0x1600; Disabled: False
B258 = TerminalEL3102: EtherCAT Terminal EL3102 2-chn Analog Input; Rail: Left; BoxNextB: LTEPHQGU; BoxPrev: SPCCPAUO; PortPrevFull: 1206/B; PortPrevShort: B; Fullname: TIID^Vertex ISC (EtherCAT)^Corner Chassis 5 L0 (EK1101)^Corner Chassis 5 L18 (EL3102); BoxAddr: 1207; Disabled: False
B259 = TerminalEL4132: EtherCAT Terminal EL4132 2-chn Analog Ouput; Rail: Left; BoxNextB: WHXODPGR; BoxPrev: TMLCPOEL; PortPrevFull: 1207/B; PortPrevShort: B; Fullname: TIID^Vertex ISC (EtherCAT)^Corner Chassis 5 L0 (EK1101)^Corner Chassis 5 L19 (EL4132); BoxAddr: 1208; Disabled: False
B260 = TerminalEL9011: EtherCAT Terminal EL9011 End; BoxType: TerminalPassive; Rail: Left; BoxPrev: LTEPHQGU; PortPrevShort: B; Fullname: TIID^Vertex ISC (EtherCAT)^Corner Chassis 5 L0 (EK1101)^Corner Chassis 5 L20 (EL9011); Disabled: False
B261 = CouplerEK1100: EtherCAT Coupler; Rail: Middle; BoxNextB: GMUWQUKR; BoxNextC: TWOPCTGM; BoxPrev: FCKUDXRC; PortPrevFull: 1190/C; PortPrevShort: C 'X2 Out'; Fullname: TIID^Vertex ISC (EtherCAT)^Corner Chassis 5 M0 (EK1100); BoxPorts: Junction; BoxAddr: 1209; Disabled: False
B262 = TerminalEL3104: EtherCAT Terminal EL3104 4-chn Analog Input; Rail: Middle; BoxNextB: BAFFDYTV; BoxPrev: RDWQKENG; PortPrevFull: 1209/B; PortPrevShort: B; Fullname: TIID^Vertex ISC (EtherCAT)^Corner Chassis 5 M0 (EK1100)^Corner Chassis 5 M1 (EL3104); BoxAddr: 1210; Disabled: False
B263 = TerminalEL3104: EtherCAT Terminal EL3104 4-chn Analog Input; Rail: Middle; BoxNextB: NSKVDFAE; BoxPrev: GMUWQUKR; PortPrevFull: 1210/B; PortPrevShort: B; Fullname: TIID^Vertex ISC (EtherCAT)^Corner Chassis 5 M0 (EK1100)^Corner Chassis 5 M2 (EL3104); BoxAddr: 1211; Disabled: False
B264 = TerminalEL3104: EtherCAT Terminal EL3104 4-chn Analog Input; Rail: Middle; BoxNextB: UUVUXVOK; BoxPrev: BAFFDYTV; PortPrevFull: 1211/B; PortPrevShort: B; Fullname: TIID^Vertex ISC (EtherCAT)^Corner Chassis 5 M0 (EK1100)^Corner Chassis 5 M3 (EL3104); BoxAddr: 1212; Disabled: False
B265 = TerminalEL4132: EtherCAT Terminal EL4132 2-chn Analog Ouput; Rail: Middle; BoxNextB: XVAGMERU; BoxPrev: NSKVDFAE; PortPrevFull: 1212/B; PortPrevShort: B; Fullname: TIID^Vertex ISC (EtherCAT)^Corner Chassis 5 M0 (EK1100)^Corner Chassis 5 M4 (EL4132); BoxAddr: 1213; Disabled: False
B266 = TerminalEL1124: EtherCAT Terminal EL1124 4-chn Digital Input; Rail: Middle; BoxNextB: NSIAPENT; BoxPrev: UUVUXVOK; PortPrevFull: 1213/B; PortPrevShort: B; Fullname: TIID^Vertex ISC (EtherCAT)^Corner Chassis 5 M0 (EK1100)^Corner Chassis 5 M5 (EL1124); BoxAddr: 1214; Disabled: False
B267 = TerminalEL2124: EtherCAT Terminal EL2124 4-chn Digital Ouput; Rail: Middle; BoxNextB: AWJEIRBS; BoxPrev: XVAGMERU; PortPrevFull: 1214/B; PortPrevShort: B; Fullname: TIID^Vertex ISC (EtherCAT)^Corner Chassis 5 M0 (EK1100)^Corner Chassis 5 M6 (EL2124); BoxAddr: 1215; Disabled: False
B268 = TerminalEL3202-0010: EtherCAT Terminal EL3202-0010 2-chn Temperature Input; Rail: Middle; BoxNextB: NQSYCRGA; BoxPrev: NSIAPENT; PortPrevFull: 1215/B; PortPrevShort: B; Fullname: TIID^Vertex ISC (EtherCAT)^Corner Chassis 5 M0 (EK1100)^Corner Chassis 5 M7 (EL3202-0010); BoxAddr: 1216; Disabled: False
B270 = TerminalEL2124: EtherCAT Terminal EL2124 4-chn Digital Ouput; Rail: Middle; BoxNextB: TUXBWAWR; BoxPrev: NQSYCRGA; PortPrevFull: 1216/B; PortPrevShort: B; Fullname: TIID^Vertex ISC (EtherCAT)^Corner Chassis 5 M0 (EK1100)^Corner Chassis 5 M9 (EL2124); BoxAddr: 1217; Disabled: False
B271 = TerminalEL2124: EtherCAT Terminal EL2124 4-chn Digital Ouput; Rail: Middle; BoxNextB: VLLCMGOC; BoxPrev: NIFPYAGY; PortPrevFull: 1217/B; PortPrevShort: B; Fullname: TIID^Vertex ISC (EtherCAT)^Corner Chassis 5 M0 (EK1100)^Corner Chassis 5 M10 (EL2124); BoxAddr: 1218; Disabled: False
B272 = TerminalEL3104: EtherCAT Terminal EL3104 4-chn Analog Input; Rail: Middle; BoxNextB: ULVFOCLO; BoxPrev: TUXBWAWR; PortPrevFull: 1218/B; PortPrevShort: B; Fullname: TIID^Vertex ISC (EtherCAT)^Corner Chassis 5 M0 (EK1100)^Corner Chassis 5 M11 (EL3104); BoxAddr: 1219; Disabled: False
B273 = TerminalEL3104: EtherCAT Terminal EL3104 4-chn Analog Input; Rail: Middle; BoxNextB: YMUWYDTP; BoxPrev: VLLCMGOC; PortPrevFull: 1219/B; PortPrevShort: B; Fullname: TIID^Vertex ISC (EtherCAT)^Corner Chassis 5 M0 (EK1100)^Corner Chassis 5 M12 (EL3104); BoxAddr: 1220; Disabled: False
B274 = TerminalEL9011: EtherCAT Terminal EL9011 End; BoxType: TerminalPassive; Rail: Middle; BoxPrev: ULVFOCLO; PortPrevShort: B; Fullname: TIID^Vertex ISC (EtherCAT)^Corner Chassis 5 M0 (EK1100)^Corner Chassis 5 M13 (EL9011); Disabled: False
B275 = CouplerEK1100: EtherCAT Coupler; Rail: Right; BoxNextB: QPVYKXBG; BoxNextC: OOGIUDKC; BoxPrev: RDWQKENG; PortPrevFull: 1209/C; PortPrevShort: C 'X2 Out'; Fullname: TIID^Vertex ISC (EtherCAT)^Corner Chassis 5 R0 (EK1100); BoxPorts: Junction; BoxAddr: 1221; Disabled: False
B276 = TerminalEL7332: EtherCAT Terminal EL7332 2-channel DC motor output stage 24 V DC, 1 A; Rail: Right; BoxNextB: XNMWPARF; BoxPrev: TWOPCTGM; PortPrevFull: 1221/B; PortPrevShort: B; Fullname: TIID^Vertex ISC (EtherCAT)^Corner Chassis 5 R0 (EK1100)^Corner Chassis 5 R1 (EL7332); BoxAddr: 1222; PDO Outputs: 0x1604,0x1605,0x1606,0x1607; PDO Inputs: 0x1A04,0x1A06; Disabled: False
B277 = TerminalEL1094: EtherCAT Terminal EL1094 4-channel digital input terminal 24 V DC, switching to negative potential; Rail: Right; BoxNextB: RHAXRSST; BoxPrev: QPVYKXBG; PortPrevFull: 1222/B; PortPrevShort: B; Fullname: TIID^Vertex ISC (EtherCAT)^Corner Chassis 5 R0 (EK1100)^Corner Chassis 5 R2 (EL1094); BoxAddr: 1223; Disabled: False
B278 = TerminalEL7332: EtherCAT Terminal EL7332 2-channel DC motor output stage 24 V DC, 1 A; Rail: Right; BoxNextB: JYHXPODE; BoxPrev: XNMWPARF; PortPrevFull: 1223/B; PortPrevShort: B; Fullname: TIID^Vertex ISC (EtherCAT)^Corner Chassis 5 R0 (EK1100)^Corner Chassis 5 R3 (EL7332); BoxAddr: 1224; PDO Outputs: 0x1604,0x1605,0x1606,0x1607; PDO Inputs: 0x1A04,0x1A06; Disabled: False
B279 = TerminalEL1094: EtherCAT Terminal EL1094 4-channel digital input terminal 24 V DC, switching to negative potential; Rail: Right; BoxNextB: STNSCHAN; BoxPrev: RHAXRSST; PortPrevFull: 1224/B; PortPrevShort: B; Fullname: TIID^Vertex ISC (EtherCAT)^Corner Chassis 5 R0 (EK1100)^Corner Chassis 5 R4 (EL1094); BoxAddr: 1225; Disabled: False
B280 = TerminalEL1094: EtherCAT Terminal EL1094 4-channel digital input terminal 24 V DC, switching to negative potential; Rail: Right; BoxNextB: WOFFUEQW; BoxPrev: JYHXPODE; PortPrevFull: 1225/B; PortPrevShort: B; Fullname: TIID^Vertex ISC (EtherCAT)^Corner Chassis 5 R0 (EK1100)^Corner Chassis 5 R5 (EL1094); BoxAddr: 1226; Disabled: False
B281 = TerminalEL2008: EtherCAT Terminal EL2008 8-channel digital output terminal 24 V DC, 0.5 A; Rail: Right; BoxNextB: YJFPNMHV; BoxPrev: STNSCHAN; PortPrevFull: 1226/B; PortPrevShort: B; Fullname: TIID^Vertex ISC (EtherCAT)^Corner Chassis 5 R0 (EK1100)^Corner Chassis 5 R6 (EL2008); BoxAddr: 1227; Disabled: False
B282 = TerminalEL1094: EtherCAT Terminal EL1094 4-channel digital input terminal 24 V DC, switching to negative potential; Rail: Right; BoxNextB: EPUSYJIS; BoxPrev: WOFFUEQW; PortPrevFull: 1227/B; PortPrevShort: B; Fullname: TIID^Vertex ISC (EtherCAT)^Corner Chassis 5 R0 (EK1100)^Corner Chassis 5 R7 (EL1094); BoxAddr: 1228; Disabled: False
B283 = TerminalEL2008: EtherCAT Terminal EL2008 8-channel digital output terminal 24 V DC, 0.5 A; Rail: Right; BoxNextB: DKMXUEGV; BoxPrev: YJFPNMHV; PortPrevFull: 1228/B; PortPrevShort: B; Fullname: TIID^Vertex ISC (EtherCAT)^Corner Chassis 5 R0 (EK1100)^Corner Chassis 5 R8 (EL2008); BoxAddr: 1229; Disabled: False
B284 = TerminalEL3104: EtherCAT Terminal EL3104 4-chn Analog Input; Rail: Right; BoxNextB: JULUELOO; BoxPrev: EPUSYJIS; PortPrevFull: 1229/B; PortPrevShort: B; Fullname: TIID^Vertex ISC (EtherCAT)^Corner Chassis 5 R0 (EK1100)^Corner Chassis 5 R9 (EL3104); BoxAddr: 1230; Disabled: False
B285 = TerminalEL3104: EtherCAT Terminal EL3104 4-chn Analog Input; Rail: Right; BoxNextB: AEBEKJLV; BoxPrev: DKMXUEGV; PortPrevFull: 1230/B; PortPrevShort: B; Fullname: TIID^Vertex ISC (EtherCAT)^Corner Chassis 5 R0 (EK1100)^Corner Chassis 5 R10 (EL3104); BoxAddr: 1231; Disabled: False
B286 = TerminalEL4134: EtherCAT Terminal EL4134 4-chn Analog Ouput; Rail: Right; BoxNextB: ICNHSMEO; BoxPrev: JULUELOO; PortPrevFull: 1231/B; PortPrevShort: B; Fullname: TIID^Vertex ISC (EtherCAT)^Corner Chassis 5 R0 (EK1100)^Corner Chassis 5 R11 (EL4134); BoxAddr: 1232; Disabled: False
B287 = TerminalEL4134: EtherCAT Terminal EL4134 4-chn Analog Ouput; Rail: Right; BoxNextB: CGVGPFCF; BoxPrev: AEBEKJLV; PortPrevFull: 1232/B; PortPrevShort: B; Fullname: TIID^Vertex ISC (EtherCAT)^Corner Chassis 5 R0 (EK1100)^Corner Chassis 5 R12 (EL4134); BoxAddr: 1233; Disabled: False
B288 = TerminalEL9410: EtherCAT Terminal EL9410 Power; Rail: Right; BoxNextB: TSURHCSJ; BoxPrev: ICNHSMEO; PortPrevFull: 1233/B; PortPrevShort: B; Fullname: TIID^Vertex ISC (EtherCAT)^Corner Chassis 5 R0 (EK1100)^Corner Chassis 5 R13 (EL9410); BoxAddr: 1234; Disabled: False
V215-V218 V223-V226 = ShutterControl_ShutterControlInStruct: ShutterControlInStruct; BoxType: Variable; Instance: H1AuxCorner Instance; PLC: H1AuxCorner; Task: AuxCStd
V219-V222 V228-V231 = ShutterControl_ShutterControlOutStruct: ShutterControlOutStruct; BoxType: Variable; Instance: H1AuxCorner Instance; PLC: H1AuxCorner; Task: AuxCStd
V232-V235 = BeamDiverter_BeamDiverterInStruct: BeamDiverterInStruct; BoxType: Variable; Instance: H1AuxCorner Instance; PLC: H1AuxCorner; Task: AuxCStd
V238 = LowNoiseVco_LowNoiseVcoInStructB: LowNoiseVcoInStruct; BoxType: Variable; Instance: H1IscCorner Instance; PLC: H1IscCorner; Task: IscCStd
V335 V376 = Auxiliary_AuxiliaryInStruct: AuxiliaryInStruct; BoxType: Variable; Instance: H1IscCorner Instance; PLC: H1IscCorner; Task: IscCStd
V336 V377 = Auxiliary_AuxiliaryOutStruct: AuxiliaryOutStruct; BoxType: Variable; Instance: H1IscCorner Instance; PLC: H1IscCorner; Task: IscCStd
V337 = PztShutter_PztShutterInStruct: PztShutterInStruct; BoxType: Variable; Instance: H1AuxCorner Instance; PLC: H1AuxCorner; Task: AuxCStd
V338-V343 V384-V387 = DCPower_DCPowerOutStruct: DCPowerOutStruct; BoxType: Variable; Instance: H1IscCorner Instance; PLC: H1IscCorner; Task: IscCStd
V344-V347 V349 V352-V355 V388-V395 = DCPower_DCPowerInStruct: DCPowerInStruct; BoxType: Variable; Instance: H1IscCorner Instance; PLC: H1IscCorner; Task: IscCStd
V348 = DCPower_DCPowerFastInStruct: DCPowerInStruct; BoxType: Variable; Instance: H1SqzCorner Instance; PLC: H1SqzCorner; Task: SqzCFast
V350 V351 = DCPower_DCPowerInStruct: DCPowerInStruct; BoxType: Variable; Instance: H1AuxCorner Instance; PLC: H1AuxCorner; Task: AuxCStd
V378 = FiberDistribution_FiberDistributionInStruct: FiberDistributionInStruct; BoxType: Variable; Instance: H1IscCorner Instance; PLC: H1IscCorner; Task: IscCStd
V379 = LowNoiseVco_LowNoiseVcoOutStruct: LowNoiseVcoOutStruct; BoxType: Variable; Instance: H1IscCorner Instance; PLC: H1IscCorner; Task: IscCStd
V382 V383 = VariableInINT: INT; PLC: H1AuxCorner; Task: AuxCStd; Instance: H1AuxCorner Instance
V396-V399 = BeamDiverter_BeamDiverterOutStruct: BeamDiverterOutStruct; BoxType: Variable; Instance: H1AuxCorner Instance; PLC: H1AuxCorner; Task: AuxCStd
V717 = TECController_TECDriverInStruct: TECDriverInStruct; BoxType: Variable; Instance: H1IscCorner Instance; PLC: H1IscCorner; Task: IscCStd
V718 = TECController_TECDriverOutStruct: TECDriverOutStruct; BoxType: Variable; Instance: H1IscCorner Instance; PLC: H1IscCorner; Task: IscCStd
V719 V896 V898 = TECController_ThermistorInStruct: ThermistorInStruct; BoxType: Variable; Instance: H1IscCorner Instance; PLC: H1IscCorner; Task: IscCStd
V720 V897 V899 = TECController_ThermistorOutStruct: ThermistorOutStruct; BoxType: Variable; Instance: H1IscCorner Instance; PLC: H1IscCorner; Task: IscCStd
V902 V903 = PztDriver_PztDriverInStruct: PztDriverInStruct; BoxType: Variable; Instance: H1SqzCorner Instance; PLC: H1SqzCorner; Task: SqzCStd
V904 V905 = PztDriver_PztDriverFastOutStruct: PztDriverOutStruct; BoxType: Variable; Instance: H1SqzCorner Instance; PLC: H1SqzCorner; Task: SqzCFast
V906 = ArrayAggregatorIn: Array [1..5] Of IscWhiteningInStruct; Instance: H1IscCorner Instance; PLC: H1IscCorner; Task: IscCStd; Lower Bound: 1; Upper Bound: 5
V907 = ArrayAggregatorOut: Array [1..5] Of IscWhiteningOutStruct; Instance: H1IscCorner Instance; PLC: H1IscCorner; Task: IscCStd; Lower Bound: 1; Upper Bound: 5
